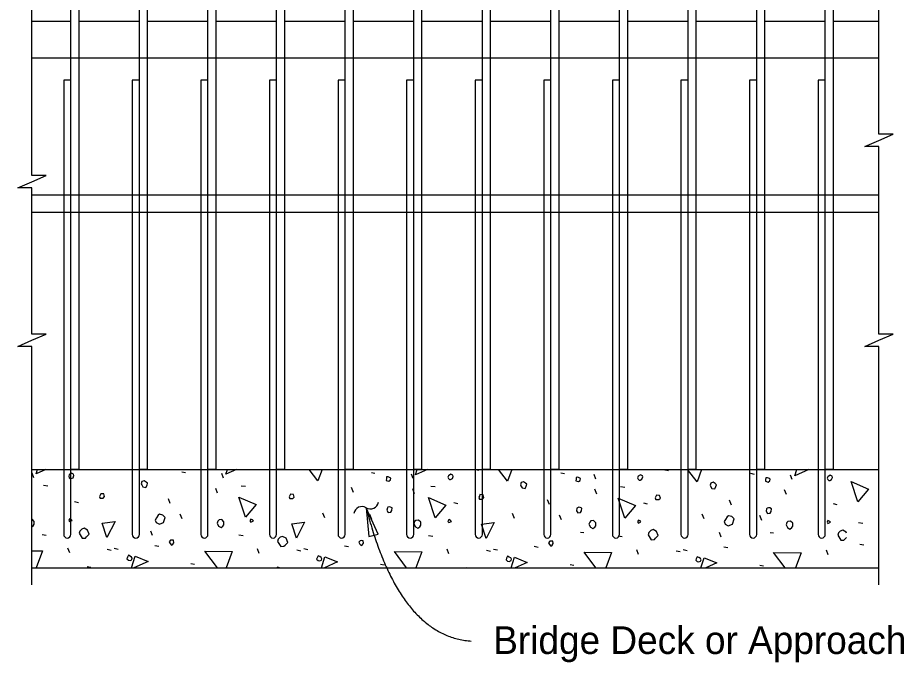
# Model space of a CAD drawing. Extents: x 120587.5 to 120659.6, y 120683.4 to 120715.5.
# Drawn here: x 120608.85 to 120615.29, y 120695.01 to 120699.71 of the extents above; entities that cross this region are included whole.
import ezdxf

# ---------------------------------------------------------------- set-up
doc = ezdxf.new("R2010")
doc.units = 0
for name, color, linetype in [('AdhocPoint_dp', 7, 'Continuous'), ('Border', 7, 'Continuous'), ('Patterning', 7, 'Continuous'), ('PlotBorder_dp', 7, 'Continuous')]:
    doc.layers.add(name, color=color, linetype=linetype)

msp = doc.modelspace()

# ---------------------------------------------------------------- linework, layer by layer
at = {"layer": 'AdhocPoint_dp'}
for points in [[(120608.952, 120699.087), (120608.952, 120701.4106), (120608.8486, 120701.4106), (120608.952, 120701.4556), (120609.0553, 120701.5006), (120608.952, 120701.5006), (120608.952, 120704.5808)], [(120615.1275, 120697.6639), (120615.1275, 120698.7724), (120615.0241, 120698.7724), (120615.1275, 120698.8174), (120615.2308, 120698.8624), (120615.1275, 120698.8624), (120615.1275, 120701.1964)], [(120608.952, 120698.087), (120608.952, 120698.4714), (120608.8487, 120698.4714), (120608.952, 120698.5164), (120609.0553, 120698.5614), (120608.952, 120698.5614), (120608.952, 120699.087)], [(120608.952, 120695.5791), (120608.952, 120697.3162), (120608.8486, 120697.3162), (120608.952, 120697.3612), (120609.0553, 120697.4062), (120608.952, 120697.4062), (120608.952, 120698.087)], [(120615.1274, 120695.5791), (120615.1274, 120697.3162), (120615.0241, 120697.3162), (120615.1274, 120697.3612), (120615.2308, 120697.4062), (120615.1274, 120697.4062), (120615.1274, 120697.6639)], [(120608.952, 120695.653), (120608.952, 120696.3496)]]:
    msp.add_lwpolyline(points, dxfattribs=at)
msp.add_lwpolyline([(120611.3898, 120696.1414), (120611.4084, 120695.931), (120611.4767, 120695.9489)], close=True, dxfattribs=at)
for centre, start, end in [((120611.3577, 120696.0901), 58.84988, 170.5771), ((120611.4194, 120696.1921), 238.84988, 350.5771)]:
    msp.add_arc(centre, 0.0596, start, end, dxfattribs=at)
msp.add_open_spline([(120611.3892, 120696.1413), (120611.6285, 120695.2055), (120612.1553, 120695.1698)], degree=2, dxfattribs=at)
at = {"layer": 'Border'}
for p, q in [((120609.236, 120699.6833), (120608.952, 120699.6833)), ((120609.736, 120699.6833), (120609.2933, 120699.6833)), ((120610.236, 120699.6833), (120609.7933, 120699.6833)), ((120610.736, 120699.6833), (120610.2933, 120699.6833)), ((120611.236, 120699.6833), (120610.7933, 120699.6833)), ((120611.736, 120699.6833), (120611.2933, 120699.6833)), ((120612.236, 120699.6833), (120611.7933, 120699.6833)), ((120612.736, 120699.6833), (120612.2933, 120699.6833)), ((120613.236, 120699.6833), (120612.7933, 120699.6833)), ((120613.736, 120699.6833), (120613.2933, 120699.6833)), ((120614.236, 120699.6833), (120613.7933, 120699.6833)), ((120614.236, 120699.6833), (120614.1385, 120699.6833)), ((120614.736, 120699.6833), (120614.2933, 120699.6833)), ((120615.1275, 120699.6833), (120614.7933, 120699.6833)), ((120615.1275, 120699.6833), (120614.8382, 120699.6833)), ((120609.236, 120699.2563), (120609.184, 120699.2563)), ((120609.184, 120699.2563), (120609.184, 120695.9464)), ((120609.236, 120695.9464), (120609.236, 120699.2563)), ((120609.736, 120699.2563), (120609.684, 120699.2563)), ((120609.684, 120699.2563), (120609.684, 120695.9464)), ((120609.736, 120695.9464), (120609.736, 120699.2563)), ((120610.236, 120699.2563), (120610.184, 120699.2563)), ((120610.184, 120699.2563), (120610.184, 120695.9464)), ((120610.236, 120695.9464), (120610.236, 120699.2563)), ((120610.736, 120699.2563), (120610.684, 120699.2563)), ((120610.684, 120699.2563), (120610.684, 120695.9464)), ((120610.736, 120695.9464), (120610.736, 120699.2563)), ((120611.236, 120699.2563), (120611.184, 120699.2563)), ((120611.184, 120699.2563), (120611.184, 120695.9464)), ((120611.236, 120695.9464), (120611.236, 120699.2563)), ((120611.736, 120699.2563), (120611.684, 120699.2563)), ((120611.684, 120699.2563), (120611.684, 120695.9464)), ((120611.736, 120695.9464), (120611.736, 120699.2563)), ((120612.236, 120699.2563), (120612.184, 120699.2563)), ((120612.184, 120699.2563), (120612.184, 120695.9464)), ((120612.236, 120695.9464), (120612.236, 120699.2563)), ((120612.736, 120699.2563), (120612.684, 120699.2563)), ((120612.684, 120699.2563), (120612.684, 120695.9464)), ((120612.736, 120695.9464), (120612.736, 120699.2563)), ((120613.236, 120699.2563), (120613.184, 120699.2563)), ((120613.184, 120699.2563), (120613.184, 120695.9464)), ((120613.236, 120695.9464), (120613.236, 120699.2563)), ((120613.736, 120699.2563), (120613.684, 120699.2563)), ((120613.684, 120699.2563), (120613.684, 120695.9464)), ((120613.736, 120695.9464), (120613.736, 120699.2563)), ((120614.236, 120699.2563), (120614.184, 120699.2563)), ((120614.184, 120699.2563), (120614.184, 120695.9464)), ((120614.236, 120695.9464), (120614.236, 120699.2563)), ((120614.736, 120699.2563), (120614.684, 120699.2563)), ((120614.684, 120699.2563), (120614.684, 120695.9464)), ((120614.736, 120695.9464), (120614.736, 120699.2563))]:
    msp.add_line(p, q, dxfattribs=at)
for points in [[(120609.236, 120704.2537), (120609.2933, 120704.2537), (120609.2933, 120696.4203), (120609.236, 120696.4203)], [(120609.736, 120704.2537), (120609.7933, 120704.2537), (120609.7933, 120696.4203), (120609.736, 120696.4203)], [(120610.236, 120704.2537), (120610.2933, 120704.2537), (120610.2933, 120696.4203), (120610.236, 120696.4203)], [(120610.736, 120704.211), (120610.7933, 120704.211), (120610.7933, 120696.4203), (120610.736, 120696.4203)], [(120611.236, 120704.1485), (120611.2933, 120704.1485), (120611.2933, 120696.4203), (120611.236, 120696.4203)], [(120611.736, 120704.086), (120611.7933, 120704.086), (120611.7933, 120696.4203), (120611.736, 120696.4203)], [(120612.236, 120704.0235), (120612.2933, 120704.0235), (120612.2933, 120696.4203), (120612.236, 120696.4203)], [(120612.736, 120703.961), (120612.7933, 120703.961), (120612.7933, 120696.4203), (120612.736, 120696.4203)], [(120613.236, 120703.8985), (120613.2933, 120703.8985), (120613.2933, 120696.4203), (120613.236, 120696.4203)], [(120613.736, 120703.836), (120613.7933, 120703.836), (120613.7933, 120696.4203), (120613.736, 120696.4203)], [(120614.236, 120703.7735), (120614.2933, 120703.7735), (120614.2933, 120696.4203), (120614.236, 120696.4203)], [(120614.736, 120703.711), (120614.7933, 120703.711), (120614.7933, 120696.4203), (120614.736, 120696.4203)]]:
    msp.add_lwpolyline(points, close=True, dxfattribs=at)
for centre in [(120609.21, 120695.9464), (120609.71, 120695.9464), (120610.21, 120695.9464), (120610.71, 120695.9464), (120611.21, 120695.9464), (120611.71, 120695.9464), (120612.21, 120695.9464), (120612.71, 120695.9464), (120613.21, 120695.9464), (120613.71, 120695.9464), (120614.21, 120695.9464), (120614.71, 120695.9464)]:
    msp.add_arc(centre, 0.026, 180, 0, dxfattribs=at)
at = {"layer": 'Patterning'}
for p, q in [((120608.9661, 120696.3602), (120608.9538, 120696.3938)), ((120610.0445, 120696.4027), (120610.071, 120696.3974)), ((120610.3485, 120696.3567), (120610.3362, 120696.3903)), ((120610.8188, 120696.4203), (120610.8276, 120696.4186)), ((120611.4269, 120696.3991), (120611.4534, 120696.3938)), ((120611.7309, 120696.3532), (120611.7186, 120696.3868)), ((120612.1835, 120696.4203), (120612.21, 120696.415)), ((120612.8093, 120696.3956), (120612.8358, 120696.3903)), ((120613.5659, 120696.4168), (120613.5924, 120696.4115)), ((120614.1917, 120696.3921), (120614.2182, 120696.3868)), ((120613.0625, 120696.3496), (120613.0501, 120696.3832)), ((120614.4957, 120696.3461), (120614.4834, 120696.3797)), ((120609.0372, 120696.3054), (120609.069, 120696.3019)), ((120610.3061, 120696.2471), (120610.292, 120696.2825)), ((120610.4776, 120696.3019), (120610.5094, 120696.2984)), ((120611.2967, 120696.2533), (120611.2825, 120696.2886)), ((120611.7423, 120696.2436), (120611.7281, 120696.2789)), ((120611.86, 120696.2984), (120611.8918, 120696.2948)), ((120613.0709, 120696.24), (120613.0568, 120696.2754)), ((120613.2424, 120696.2948), (120613.2742, 120696.2913)), ((120614.4533, 120696.2365), (120614.4392, 120696.2718)), ((120609.9614, 120696.1711), (120609.9473, 120696.2064)), ((120612.7262, 120696.164), (120612.712, 120696.1994)), ((120614.0523, 120696.1605), (120614.0382, 120696.1958)), ((120609.2631, 120696.187), (120609.2914, 120696.1799)), ((120612.0279, 120696.1799), (120612.0562, 120696.1729)), ((120613.4103, 120696.1764), (120613.4386, 120696.1693)), ((120614.7927, 120696.1729), (120614.821, 120696.1658)), ((120610.048, 120696.0597), (120610.0339, 120696.0951)), ((120611.0875, 120696.0668), (120611.0733, 120696.1021)), ((120611.4304, 120696.0562), (120611.4163, 120696.0915)), ((120612.4699, 120696.0633), (120612.4557, 120696.0986)), ((120612.8128, 120696.0526), (120612.7987, 120696.088)), ((120613.8523, 120696.0597), (120613.8381, 120696.0951)), ((120614.2736, 120696.0491), (120614.2595, 120696.0845)), ((120614.9783, 120696.0329), (120615.0101, 120696.0294)), ((120609.0274, 120695.9466), (120609.0574, 120695.9413)), ((120609.8306, 120695.9377), (120609.8182, 120695.9713)), ((120610.4617, 120695.943), (120610.4917, 120695.9377)), ((120611.8441, 120695.9395), (120611.8741, 120695.9342)), ((120612.9507, 120695.9643), (120612.9754, 120695.9607)), ((120613.2265, 120695.936), (120613.2565, 120695.9307)), ((120613.9778, 120695.9271), (120613.9654, 120695.9607)), ((120614.3331, 120695.9607), (120614.3578, 120695.9572)), ((120614.988, 120695.8762), (120615.018, 120695.8709)), ((120609.2278, 120695.8122), (120609.2154, 120695.8458)), ((120609.5018, 120695.8387), (120609.5301, 120695.8317)), ((120609.553, 120695.8476), (120609.5813, 120695.8405)), ((120609.8483, 120695.867), (120609.8783, 120695.8617)), ((120610.6102, 120695.8087), (120610.5978, 120695.8423)), ((120610.8842, 120695.8352), (120610.9125, 120695.8281)), ((120610.9354, 120695.844), (120610.9637, 120695.837)), ((120611.2307, 120695.8635), (120611.2607, 120695.8582)), ((120611.9926, 120695.8052), (120611.9802, 120695.8387)), ((120612.2666, 120695.8317), (120612.2949, 120695.8246)), ((120612.3178, 120695.8405), (120612.3461, 120695.8334)), ((120612.6131, 120695.86), (120612.6431, 120695.8547)), ((120613.375, 120695.8016), (120613.3626, 120695.8352)), ((120613.649, 120695.8281), (120613.6772, 120695.8211)), ((120613.7002, 120695.837), (120613.7285, 120695.8299)), ((120613.9954, 120695.8564), (120614.0255, 120695.8511)), ((120614.7574, 120695.7981), (120614.745, 120695.8317)), ((120609.3551, 120695.7132), (120609.3816, 120695.7079)), ((120610.1117, 120695.7344), (120610.1382, 120695.7291)), ((120610.7375, 120695.7097), (120610.764, 120695.7044)), ((120611.4941, 120695.7309), (120611.5206, 120695.7256)), ((120612.1198, 120695.7062), (120612.1323, 120695.7037)), ((120612.8765, 120695.7274), (120612.903, 120695.7221)), ((120614.2588, 120695.7238), (120614.2854, 120695.7185))]:
    msp.add_line(p, q, dxfattribs=at)
for points in [[(120608.9838, 120696.3885), (120608.9936, 120696.4203)], [(120609.0547, 120696.4203), (120608.9838, 120696.3885)], [(120609.2313, 120696.3532), (120609.2384, 120696.3532), (120609.2525, 120696.3602), (120609.2578, 120696.3761), (120609.2561, 120696.385), (120609.2419, 120696.3921), (120609.2242, 120696.3814), (120609.2207, 120696.3708), (120609.2242, 120696.3602), (120609.2313, 120696.3532)], [(120610.3662, 120696.385), (120610.3771, 120696.4203)], [(120610.4449, 120696.4203), (120610.3662, 120696.385)], [(120611.0362, 120696.3373), (120610.9731, 120696.4203)], [(120611.0673, 120696.4203), (120611.0362, 120696.3373)], [(120611.7486, 120696.3814), (120611.7606, 120696.4203)], [(120611.8352, 120696.4203), (120611.7486, 120696.3814)], [(120611.9961, 120696.3461), (120612.0032, 120696.3461), (120612.0173, 120696.3532), (120612.0226, 120696.3691), (120612.0209, 120696.3779), (120612.0067, 120696.385), (120611.989, 120696.3744), (120611.9855, 120696.3638), (120611.989, 120696.3532), (120611.9961, 120696.3461)], [(120612.4186, 120696.3337), (120612.3528, 120696.4203)], [(120612.451, 120696.4203), (120612.4186, 120696.3337)], [(120613.801, 120696.3302), (120613.7325, 120696.4203)], [(120613.8347, 120696.4203), (120613.801, 120696.3302)], [(120614.5134, 120696.3744), (120614.5275, 120696.4203)], [(120614.6157, 120696.4203), (120614.5134, 120696.3744)], [(120609.7528, 120696.309), (120609.7616, 120696.2931), (120609.7829, 120696.2895), (120609.7917, 120696.3054), (120609.7952, 120696.3196), (120609.7864, 120696.3284), (120609.7705, 120696.3373), (120609.7546, 120696.332), (120609.7493, 120696.316), (120609.7528, 120696.309)], [(120611.5347, 120696.3408), (120611.5542, 120696.3355), (120611.5665, 120696.3443), (120611.5683, 120696.3567), (120611.5648, 120696.3602), (120611.5506, 120696.3673), (120611.5383, 120696.3655), (120611.5365, 120696.3532), (120611.5347, 120696.3408)], [(120612.5176, 120696.3019), (120612.5264, 120696.286), (120612.5476, 120696.2825), (120612.5565, 120696.2984), (120612.56, 120696.3125), (120612.5512, 120696.3213), (120612.5353, 120696.3302), (120612.5194, 120696.3249), (120612.5141, 120696.309), (120612.5176, 120696.3019)], [(120612.9171, 120696.3373), (120612.9366, 120696.332), (120612.9489, 120696.3408), (120612.9507, 120696.3532), (120612.9472, 120696.3567), (120612.933, 120696.3638), (120612.9206, 120696.362), (120612.9189, 120696.3496), (120612.9171, 120696.3373)], [(120613.3785, 120696.3426), (120613.3856, 120696.3426), (120613.3997, 120696.3496), (120613.405, 120696.3655), (120613.4032, 120696.3744), (120613.3891, 120696.3814), (120613.3714, 120696.3708), (120613.3679, 120696.3602), (120613.3714, 120696.3496), (120613.3785, 120696.3426)], [(120613.9, 120696.2984), (120613.9088, 120696.2825), (120613.93, 120696.2789), (120613.9389, 120696.2948), (120613.9424, 120696.309), (120613.9336, 120696.3178), (120613.9177, 120696.3266), (120613.9018, 120696.3213), (120613.8965, 120696.3054), (120613.9, 120696.2984)], [(120614.2995, 120696.3337), (120614.3189, 120696.3284), (120614.3313, 120696.3373), (120614.3331, 120696.3496), (120614.3296, 120696.3532), (120614.3154, 120696.3602), (120614.303, 120696.3585), (120614.3013, 120696.3461), (120614.2995, 120696.3337)], [(120614.7609, 120696.339), (120614.768, 120696.339), (120614.7821, 120696.3461), (120614.7874, 120696.362), (120614.7856, 120696.3708), (120614.7715, 120696.3779), (120614.7538, 120696.3673), (120614.7503, 120696.3567), (120614.7538, 120696.3461), (120614.7609, 120696.339)], [(120614.9728, 120696.1848), (120614.9251, 120696.3315), (120615.0506, 120696.2767), (120614.9728, 120696.1848)], [(120609.4505, 120696.2117), (120609.4717, 120696.2117), (120609.4823, 120696.2224), (120609.477, 120696.2418), (120609.4541, 120696.2436), (120609.4505, 120696.233), (120609.4452, 120696.2241), (120609.4505, 120696.2117), (120609.447, 120696.2153)], [(120610.5094, 120696.0721), (120610.4617, 120696.2188), (120610.5872, 120696.164), (120610.5094, 120696.0721)], [(120610.8329, 120696.2082), (120610.8541, 120696.2082), (120610.8647, 120696.2188), (120610.8594, 120696.2383), (120610.8364, 120696.24), (120610.8329, 120696.2294), (120610.8276, 120696.2206), (120610.8329, 120696.2082), (120610.8294, 120696.2117)], [(120611.8918, 120696.0686), (120611.8441, 120696.2153), (120611.9696, 120696.1605), (120611.8918, 120696.0686)], [(120612.2153, 120696.2047), (120612.2365, 120696.2047), (120612.2471, 120696.2153), (120612.2418, 120696.2347), (120612.2188, 120696.2365), (120612.2153, 120696.2259), (120612.21, 120696.217), (120612.2153, 120696.2047), (120612.2118, 120696.2082)], [(120613.2742, 120696.065), (120613.2265, 120696.2117), (120613.352, 120696.1569), (120613.2742, 120696.065)], [(120613.5019, 120696.2011), (120613.5232, 120696.2011), (120613.5338, 120696.2117), (120613.5285, 120696.2312), (120613.5055, 120696.233), (120613.5019, 120696.2224), (120613.4966, 120696.2135), (120613.5019, 120696.2011), (120613.4984, 120696.2047)], [(120611.54, 120696.1234), (120611.5489, 120696.1074), (120611.5683, 120696.1092), (120611.5771, 120696.1216), (120611.5789, 120696.141), (120611.5665, 120696.1463), (120611.5577, 120696.1481), (120611.5471, 120696.1446), (120611.5436, 120696.141), (120611.54, 120696.1234)], [(120612.9224, 120696.1198), (120612.9313, 120696.1039), (120612.9507, 120696.1057), (120612.9595, 120696.1181), (120612.9613, 120696.1375), (120612.9489, 120696.1428), (120612.9401, 120696.1446), (120612.9295, 120696.141), (120612.9259, 120696.1375), (120612.9224, 120696.1198)], [(120614.3048, 120696.1163), (120614.3136, 120696.1004), (120614.3331, 120696.1021), (120614.3419, 120696.1145), (120614.3437, 120696.134), (120614.3313, 120696.1393), (120614.3225, 120696.141), (120614.3119, 120696.1375), (120614.3083, 120696.134), (120614.3048, 120696.1163)], [(120609.8589, 120696.0332), (120609.8819, 120696.0208), (120609.9119, 120696.0332), (120609.9243, 120696.0703), (120609.9066, 120696.088), (120609.8836, 120696.0933), (120609.873, 120696.0862), (120609.8606, 120696.0668), (120609.8518, 120696.0509), (120609.8589, 120696.0332)], [(120614.0061, 120696.0226), (120614.029, 120696.0102), (120614.0591, 120696.0226), (120614.0715, 120696.0597), (120614.0538, 120696.0774), (120614.0308, 120696.0827), (120614.0202, 120696.0756), (120614.0078, 120696.0562), (120613.999, 120696.0403), (120614.0061, 120696.0226)], [(120608.952, 120696.0023), (120608.9626, 120696.0102), (120608.9697, 120696.0208), (120608.9697, 120696.042), (120608.9538, 120696.0579), (120608.952, 120696.0578)], [(120609.226, 120696.0403), (120609.2455, 120696.0491), (120609.2384, 120696.0562), (120609.226, 120696.0615), (120609.2207, 120696.0491), (120609.226, 120696.0403)], [(120609.4982, 120695.9236), (120609.4647, 120696.0279), (120609.5584, 120696.0403), (120609.4982, 120695.9236)], [(120610.3026, 120696.0279), (120610.3132, 120696.0067), (120610.3309, 120695.9961), (120610.345, 120696.0067), (120610.3521, 120696.0173), (120610.3521, 120696.0385), (120610.3362, 120696.0544), (120610.3167, 120696.0526), (120610.3079, 120696.0438), (120610.3026, 120696.0279)], [(120610.5472, 120696.0367), (120610.5666, 120696.0456), (120610.5596, 120696.0526), (120610.5472, 120696.0579), (120610.5419, 120696.0456), (120610.5472, 120696.0367)], [(120610.8806, 120695.9201), (120610.8471, 120696.0244), (120610.9407, 120696.0367), (120610.8806, 120695.9201)], [(120611.7373, 120696.0244), (120611.7479, 120696.0031), (120611.7656, 120695.9925), (120611.7797, 120696.0031), (120611.7868, 120696.0138), (120611.7868, 120696.035), (120611.7709, 120696.0509), (120611.7515, 120696.0491), (120611.7426, 120696.0403), (120611.7373, 120696.0244)], [(120611.9908, 120696.0332), (120612.0102, 120696.042), (120612.0032, 120696.0491), (120611.9908, 120696.0544), (120611.9855, 120696.042), (120611.9908, 120696.0332)], [(120612.263, 120695.9165), (120612.2294, 120696.0208), (120612.3231, 120696.0332), (120612.263, 120695.9165)], [(120613.0132, 120696.0208), (120613.0238, 120695.9996), (120613.0415, 120695.989), (120613.0557, 120695.9996), (120613.0627, 120696.0102), (120613.0627, 120696.0314), (120613.0468, 120696.0473), (120613.0274, 120696.0456), (120613.0185, 120696.0367), (120613.0132, 120696.0208)], [(120613.3732, 120696.0297), (120613.3926, 120696.0385), (120613.3856, 120696.0456), (120613.3732, 120696.0509), (120613.3679, 120696.0385), (120613.3732, 120696.0297)], [(120614.4498, 120696.0173), (120614.4604, 120695.9961), (120614.478, 120695.9855), (120614.4922, 120695.9961), (120614.4993, 120696.0067), (120614.4993, 120696.0279), (120614.4834, 120696.0438), (120614.4639, 120696.042), (120614.4551, 120696.0332), (120614.4498, 120696.0173)], [(120614.7556, 120696.0261), (120614.775, 120696.035), (120614.768, 120696.042), (120614.7556, 120696.0473), (120614.7503, 120696.035), (120614.7556, 120696.0261)], [(120609.2967, 120695.9554), (120609.3197, 120695.9183), (120609.3427, 120695.9201), (120609.3515, 120695.9289), (120609.371, 120695.9483), (120609.3586, 120695.9784), (120609.3338, 120695.9925), (120609.3162, 120695.9855), (120609.302, 120695.9713), (120609.2967, 120695.9554)], [(120613.4439, 120695.9448), (120613.4669, 120695.9077), (120613.4899, 120695.9095), (120613.4987, 120695.9183), (120613.5181, 120695.9377), (120613.5058, 120695.9678), (120613.481, 120695.9819), (120613.4633, 120695.9749), (120613.4492, 120695.9607), (120613.4439, 120695.9448)], [(120614.8912, 120695.9568), (120614.8882, 120695.9643), (120614.8634, 120695.9784), (120614.8457, 120695.9713), (120614.8316, 120695.9572), (120614.8263, 120695.9413)], [(120614.8263, 120695.9413), (120614.8493, 120695.9042), (120614.8723, 120695.9059), (120614.8811, 120695.9148), (120614.8912, 120695.9249)], [(120609.9596, 120695.8794), (120609.9702, 120695.8688), (120609.9808, 120695.8759), (120609.9879, 120695.8865), (120609.9844, 120695.9042), (120609.9755, 120695.9059), (120609.9632, 120695.9042), (120609.9526, 120695.8935), (120609.9596, 120695.8794)], [(120610.7429, 120695.8957), (120610.7659, 120695.8586), (120610.7889, 120695.8604), (120610.7977, 120695.8692), (120610.8172, 120695.8886), (120610.8048, 120695.9187), (120610.78, 120695.9328), (120610.7624, 120695.9258), (120610.7482, 120695.9116), (120610.7429, 120695.8957)], [(120611.342, 120695.8759), (120611.3526, 120695.8653), (120611.3632, 120695.8723), (120611.3703, 120695.8829), (120611.3668, 120695.9006), (120611.3579, 120695.9024), (120611.3456, 120695.9006), (120611.335, 120695.89), (120611.342, 120695.8759)], [(120612.7244, 120695.8723), (120612.735, 120695.8617), (120612.7456, 120695.8688), (120612.7527, 120695.8794), (120612.7492, 120695.8971), (120612.7403, 120695.8988), (120612.728, 120695.8971), (120612.7174, 120695.8865), (120612.7244, 120695.8723)], [(120608.952, 120695.8271), (120609.0298, 120695.8264), (120608.9839, 120695.7037)], [(120610.3043, 120695.7037), (120610.2124, 120695.8246), (120610.4122, 120695.8228), (120610.3676, 120695.7037)], [(120611.684, 120695.7037), (120611.5948, 120695.8211), (120611.7946, 120695.8193), (120611.7514, 120695.7037)], [(120613.0637, 120695.7037), (120612.9772, 120695.8175), (120613.177, 120695.8158), (120613.1351, 120695.7037)], [(120614.4435, 120695.7037), (120614.3596, 120695.814), (120614.5594, 120695.8122), (120614.5188, 120695.7037)], [(120609.6556, 120695.7592), (120609.668, 120695.7574), (120609.6803, 120695.7627), (120609.6839, 120695.7733), (120609.6786, 120695.7822), (120609.668, 120695.7892), (120609.6556, 120695.7946), (120609.6485, 120695.7804), (120609.645, 120695.7698), (120609.6556, 120695.7592)], [(120609.6793, 120695.7037), (120609.7051, 120695.7875), (120609.7988, 120695.7504), (120609.6949, 120695.7037)], [(120611.038, 120695.7557), (120611.0503, 120695.7539), (120611.0627, 120695.7592), (120611.0663, 120695.7698), (120611.061, 120695.7786), (120611.0503, 120695.7857), (120611.038, 120695.791), (120611.0309, 120695.7769), (120611.0274, 120695.7663), (120611.038, 120695.7557)], [(120611.0628, 120695.7037), (120611.0875, 120695.7839), (120611.1812, 120695.7468), (120611.0851, 120695.7037)], [(120612.4204, 120695.7521), (120612.4327, 120695.7504), (120612.4451, 120695.7557), (120612.4487, 120695.7663), (120612.4433, 120695.7751), (120612.4327, 120695.7822), (120612.4204, 120695.7875), (120612.4133, 120695.7733), (120612.4098, 120695.7627), (120612.4204, 120695.7521)], [(120612.4463, 120695.7037), (120612.4699, 120695.7804), (120612.5636, 120695.7433), (120612.4754, 120695.7037)], [(120613.8028, 120695.7486), (120613.8151, 120695.7468), (120613.8275, 120695.7521), (120613.831, 120695.7627), (120613.8257, 120695.7716), (120613.8151, 120695.7786), (120613.8028, 120695.7839), (120613.7957, 120695.7698), (120613.7922, 120695.7592), (120613.8028, 120695.7486)], [(120613.8297, 120695.7037), (120613.8523, 120695.7769), (120613.9459, 120695.7397), (120613.8657, 120695.7037)]]:
    msp.add_lwpolyline(points, dxfattribs=at)
at = {"layer": 'PlotBorder_dp'}
for p, q in [((120608.952, 120699.4204), (120615.1275, 120699.4204)), ((120608.952, 120698.4203), (120615.1275, 120698.4203)), ((120608.952, 120698.2953), (120615.1275, 120698.2953)), ((120608.952, 120696.4203), (120615.1275, 120696.4203)), ((120608.952, 120695.7037), (120615.1275, 120695.7037))]:
    msp.add_line(p, q, dxfattribs=at)

# ---------------------------------------------------------------- texts
at = {"layer": 'AdhocPoint_dp'}
msp.add_text('Bridge Deck or Approach Slab', height=0.2016, dxfattribs=at).set_placement((120612.3155, 120695.0756))

doc.saveas('drawing.dxf')
